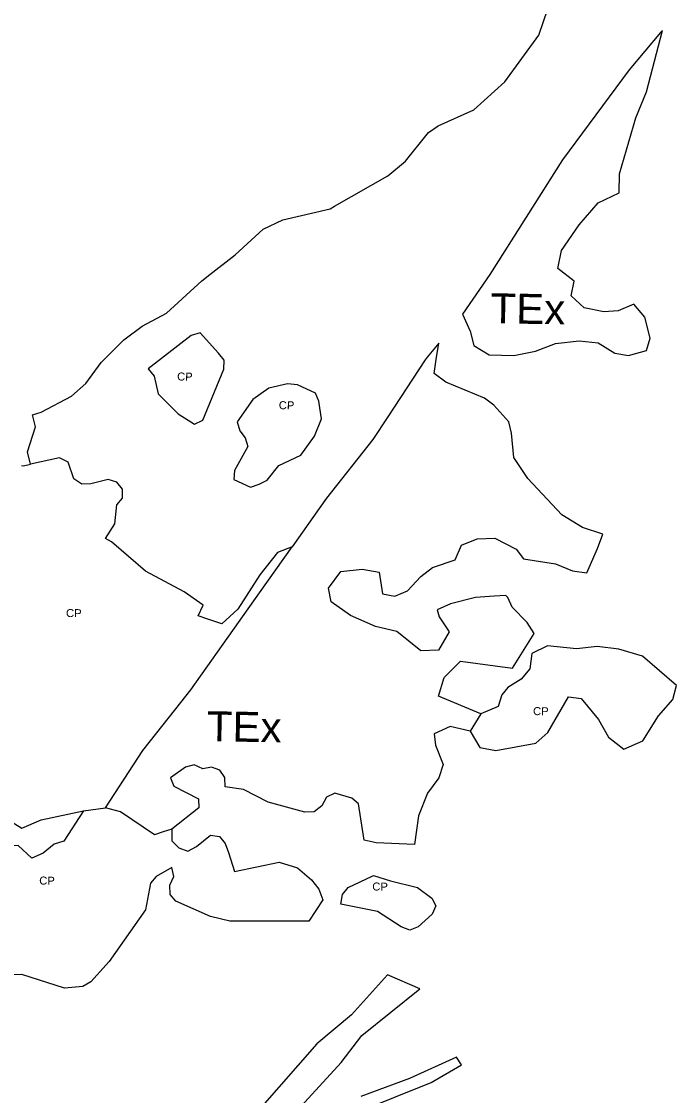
# Model space of a CAD drawing. Extents: x 713589 to 726391, y 7177764 to 7191819.
# Drawn here: x 718290 to 718814, y 7181104 to 7181963 of the extents above; entities that cross this region are included whole.
import ezdxf
from ezdxf.enums import TextEntityAlignment as Align

# ---------------------------------------------------------------- set-up
doc = ezdxf.new("R2010")
doc.units = 0
doc.header["$LTSCALE"] = 2.6
doc.layers.add('63', color=7, linetype='Continuous', lineweight=25)

msp = doc.modelspace()

# ---------------------------------------------------------------- linework, layer by layer
at = {"layer": '63'}
msp.add_line((718339.19, 7181331.99), (718356.85, 7181334.32), dxfattribs=at)
for points in [[(718296.95, 7181609.32), (718294.47, 7181619.24), (718300.73, 7181639.31), (718298.51, 7181648.87), (718305.33, 7181650.86), (718329.63, 7181663.84), (718341.04, 7181673.88), (718353.48, 7181690.67), (718371.46, 7181708.74), (718386.3, 7181719.61), (718405.7, 7181730.09), (718433.97, 7181756.09), (718440.35, 7181761.05), (718460.56, 7181776.76), (718482.9, 7181797.23), (718498.77, 7181804.82), (718536.54, 7181813.67), (718540.02, 7181815.67), (718582.63, 7181840.11), (718596.93, 7181851.77), (718615.16, 7181874.59), (718622.99, 7181880.12), (718651.65, 7181892.85), (718676.38, 7181915.13), (718703.48, 7181952.5), (718710.68, 7181973.51)], [(718657.12, 7181409.62), (718623.2, 7181423.78), (718627.81, 7181438.58), (718640.97, 7181451.75), (718682.44, 7181446.14), (718699.88, 7181473.78), (718694.29, 7181482.67), (718682.12, 7181494.85), (718678.83, 7181502.74), (718677.24, 7181504.28), (718667.75, 7181503.69), (718652.83, 7181502.75), (718632.76, 7181497.49), (718622.22, 7181492.88), (718623.87, 7181487.29), (718631.76, 7181475.11), (718623.21, 7181460.63), (718609.06, 7181459.98), (718589.97, 7181475.45), (718572.86, 7181479.4), (718552.79, 7181488.29), (718537.33, 7181499.15), (718535.35, 7181510.01), (718545.23, 7181523.5), (718562.34, 7181525.47), (718575.83, 7181522.84), (718578.46, 7181505.72), (718588.33, 7181503.75), (718598.53, 7181508.02), (718609.07, 7181519.54), (718618.61, 7181526.78), (718636.71, 7181532.7), (718641.65, 7181544.54), (718654.15, 7181549.48), (718668.3, 7181550.13), (718685.41, 7181541.24), (718691.4, 7181533.69), (718717, 7181529.72), (718730.49, 7181524.13), (718742.01, 7181522.48), (718750.57, 7181541.89), (718754.85, 7181553.41), (718738.4, 7181558.68), (718721.95, 7181568.88), (718694.64, 7181597.84), (718683.45, 7181614.63), (718681.81, 7181634.04), (718679.51, 7181643.26), (718667.67, 7181656.42), (718660.1, 7181662.02), (718629.17, 7181674.86), (718619.95, 7181681.77), (718621.55, 7181692.95), (718623.44, 7181706.15), (718614.23, 7181694.83), (718612.65, 7181692.89), (718582.74, 7181647.22), (718570.85, 7181629.06), (718533.65, 7181582.01), (718527.86, 7181573.84), (718506.25, 7181543.33)], [(718289.53, 7181608.38), (718291.17, 7181608.08), (718296.95, 7181609.32)], [(718506.25, 7181543.33), (718494.42, 7181538.65), (718480.27, 7181520.88), (718462.82, 7181493.24), (718449.99, 7181481.72), (718438.68, 7181485.42), (718430.89, 7181487.98), (718434.96, 7181496.47), (718419.9, 7181507.23), (718388.9, 7181523.79), (718361.59, 7181547.16), (718356.89, 7181549.95), (718364.22, 7181561.64), (718365.87, 7181576.77), (718370.48, 7181582.04), (718370.48, 7181589.28), (718365.88, 7181594.87), (718358.97, 7181597.18), (718345.14, 7181593.56), (718337.9, 7181593.23), (718331.65, 7181597.51), (718327.05, 7181611), (718320.14, 7181614.3), (718296.95, 7181609.32)], [(718356.85, 7181334.32), (718386.85, 7181380.32), (718413.11, 7181413.58), (718425.03, 7181428.68), (718463.35, 7181482.77), (718480.15, 7181506.49), (718506.25, 7181543.33)], [(718648.53, 7181395.72), (718632.74, 7181399.42), (718619.9, 7181393.5), (718620.89, 7181384.62), (718627.14, 7181369.15), (718623.52, 7181358.29), (718614.44, 7181346.2), (718607.39, 7181328.02), (718603.96, 7181305.1), (718573.47, 7181306.39), (718563.73, 7181308.54), (718559.34, 7181337.57), (718554.08, 7181342.18), (718540.26, 7181346.13), (718533.68, 7181342.84), (718530.06, 7181335.93), (718523.8, 7181331.33), (718516.24, 7181331), (718486.95, 7181338.9), (718467.21, 7181349.11), (718452.73, 7181351.08), (718452.4, 7181358.65), (718448.45, 7181364.58), (718441.54, 7181366.88), (718434.63, 7181365.57), (718427.72, 7181368.86), (718420.81, 7181366.88), (718408.96, 7181358.33), (718411.59, 7181351.75), (718431.34, 7181341.54), (718431.66, 7181334.3), (718409.81, 7181317.24)], [(718167.19, 7181312.85), (718178.61, 7181323.82), (718192.43, 7181326.12), (718209.21, 7181321.51), (718216.45, 7181334.67), (718229.62, 7181345.53), (718250.68, 7181348.81), (718267.46, 7181354.08), (718272.07, 7181346.51), (718273.05, 7181336.64), (718278.65, 7181325.12), (718289.83, 7181318.2), (718305.3, 7181324.78), (718339.19, 7181331.99)], [(718409.81, 7181317.24), (718402.99, 7181315.08), (718395.97, 7181312.85), (718368.87, 7181331.08), (718356.85, 7181334.32)], [(718339.19, 7181331.99), (718323.57, 7181307.67), (718315.83, 7181305.37), (718306.94, 7181298.13), (718298.05, 7181294.18), (718286.87, 7181304.38), (718279.3, 7181304.06), (718269.75, 7181285.3), (718248.69, 7181280.7), (718230.59, 7181287.28), (718208.24, 7181285.42)], [(718409.81, 7181317.24), (718409.94, 7181307.98), (718415.53, 7181302.39), (718422.77, 7181299.75), (718429.68, 7181303.37), (718440.87, 7181312.58), (718448.11, 7181311.6), (718452.72, 7181306), (718455.35, 7181298.76), (718460.1, 7181283.41), (718495.89, 7181290.92), (718510.41, 7181286.51), (718521.65, 7181276.93), (718527.45, 7181269.29), (718530.83, 7181260.77), (718519.51, 7181243.79), (718456.33, 7181243.81), (718440.86, 7181247.43), (718413.22, 7181259.61), (718408.62, 7181265.2), (718408.29, 7181272.44), (718411.58, 7181279.35), (718409.94, 7181286.59), (718397.43, 7181279.36), (718392.82, 7181274.09), (718388.87, 7181252.7), (718359.91, 7181211.57), (718345.09, 7181195.12), (718338.84, 7181191.5), (718324.03, 7181190.19), (718289.81, 7181201.06), (718266.4, 7181200.41)], [(718501.71, 7181082.88), (718545.49, 7181130.59), (718561.94, 7181152.3), (718608.4, 7181189.73), (718582.45, 7181200.87), (718553.72, 7181168.76), (718526.07, 7181145.73), (718450.04, 7181058.87)], [(718557.66, 7181090.77), (718617.55, 7181114.78), (718641.58, 7181128.93), (718637.63, 7181134.85), (718600.11, 7181117.75), (718561.28, 7181103.6)]]:
    msp.add_lwpolyline(points, dxfattribs=at)
for points in [[(718648.59, 7181715.66), (718651.55, 7181704.14), (718663.72, 7181696.9), (718683.47, 7181696.24), (718700.91, 7181699.85), (718717.03, 7181705.77), (718735.79, 7181708.07), (718750.93, 7181706.43), (718764.42, 7181698.2), (718775.28, 7181696.22), (718789.76, 7181700.17), (718792.72, 7181710.04), (718788.45, 7181726.82), (718779.56, 7181737.35), (718767.06, 7181732.09), (718755.54, 7181731.11), (718739.75, 7181734.4), (718729.55, 7181743.94), (718731.85, 7181755.79), (718718.69, 7181765.99), (718721.65, 7181780.14), (718735.81, 7181800.87), (718750.95, 7181818.31), (718767.73, 7181826.53), (718768.06, 7181841.67), (718781.23, 7181886.42), (718789.79, 7181907.15), (718802.56, 7181956.33), (718800.93, 7181954.8), (718775.91, 7181924.86), (718722.59, 7181852.8), (718664.33, 7181761), (718642.39, 7181729.42)], [(718451.45, 7181685.35), (718451.78, 7181692.59), (718447.17, 7181698.19), (718432.7, 7181714.31), (718425.46, 7181712.34), (718391.05, 7181685.58), (718395.84, 7181679.77), (718399.12, 7181665.62), (718414.92, 7181649.49), (718428.08, 7181641.26), (718434.66, 7181644.55)], [(718464.27, 7181635.99), (718468.55, 7181630.39), (718470.85, 7181623.48), (718459.99, 7181604.4), (718459.66, 7181597.16), (718472.82, 7181590.9), (718479.73, 7181593.21), (718486.32, 7181596.5), (718495.53, 7181608.34), (718513.11, 7181616.41), (718524.16, 7181631.7), (718529.76, 7181645.52), (718527.46, 7181659.67), (718524.83, 7181666.25), (718510.35, 7181672.84), (718502.45, 7181673.5), (718487.64, 7181670.21), (718474.81, 7181661), (718462.3, 7181643.23)], [(718648.53, 7181395.72), (718656.43, 7181382.64), (718669.26, 7181380.33), (718701.18, 7181386.25), (718710.73, 7181394.8), (718727.19, 7181423.1), (718737.39, 7181421.78), (718751.2, 7181405), (718759.43, 7181390.85), (718771.6, 7181381.3), (718786.74, 7181387.88), (718799.25, 7181407.95), (718810.77, 7181421.11), (718813.73, 7181432.3), (718786.42, 7181455.67), (718767.67, 7181461.27), (718750.23, 7181463.57), (718733.77, 7181461.6), (718710.41, 7181463.91), (718697.9, 7181457.99), (718696.26, 7181445.48), (718689.35, 7181437.26), (718678.81, 7181430.68), (718673.88, 7181424.76), (718670.91, 7181415.54), (718657.12, 7181409.62)], [(718574.47, 7181251.35), (718545.18, 7181257.28), (718546.5, 7181265.18), (718551.11, 7181270.77), (718570.16, 7181279.83), (718571.18, 7181280.31), (718585, 7181276.11), (718606.39, 7181270.76), (718617.91, 7181262.2), (718621.2, 7181255.95), (718618.23, 7181249.37), (718607.04, 7181239.17), (718600.46, 7181236.54), (718593.55, 7181239.17)]]:
    msp.add_lwpolyline(points, close=True, dxfattribs=at)

# ---------------------------------------------------------------- texts
at = {"layer": '63', "width": 1.05}
for s, height, p in [('TEx', 24, (718694.59, 7181721.61)), ('CP', 6.4, (718420.35, 7181676.2)), ('CP', 6.4, (718501.71, 7181653.26)), ('CP', 6.4, (718331.48, 7181486.99)), ('TEx', 24, (718467.63, 7181387.25)), ('CP', 6.4, (718705.13, 7181408.53)), ('CP', 6.4, (718310.02, 7181272.96)), ('CP', 6.4, (718576.52, 7181268.21))]:
    msp.add_text(s, height=height, rotation=359.062, dxfattribs=at).set_placement(p, align=Align.CENTER)

doc.saveas('drawing.dxf')
